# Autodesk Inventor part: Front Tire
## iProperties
Shininess: 20.0
Angle Display Precision: 2
Document Length Units: 11269
Document Angle Units: 11279
Document Time Units: 11290
Document Mass Units: 11283
Document Length Units Precision: 3
Document Angle Units Precision: 2
Compacted: True
Created: 2001-08
Part Number: Front Tire
Document SubType Name: Modeling
Designer: Martin Budgell
Density: 0.0
Volumn: 0.0
Area: 0.0
PropertySet Name: Model Information
Control State: 0
Master: False
Checked Out: False
Author: Martin Budgell
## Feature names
1. Revolution1
2. Extrusion1
3. Circular Pattern1
